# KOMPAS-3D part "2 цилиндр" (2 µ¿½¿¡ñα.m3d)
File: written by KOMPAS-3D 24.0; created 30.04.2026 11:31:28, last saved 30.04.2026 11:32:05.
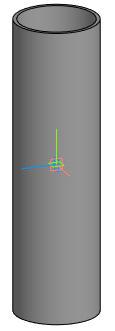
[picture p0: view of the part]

Document properties: Автор: USG_411; Полное имя файла: C:\Users\USG_411\Desktop\ИА-2904_411-12\Балка\2 цилиндр.m3d

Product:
- Part/product: 2 цилиндр
    Масса: 167.826393

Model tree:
1. Эскиз:1
2. Элемент выдавливания:1
     Расстояние 1 = 1250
